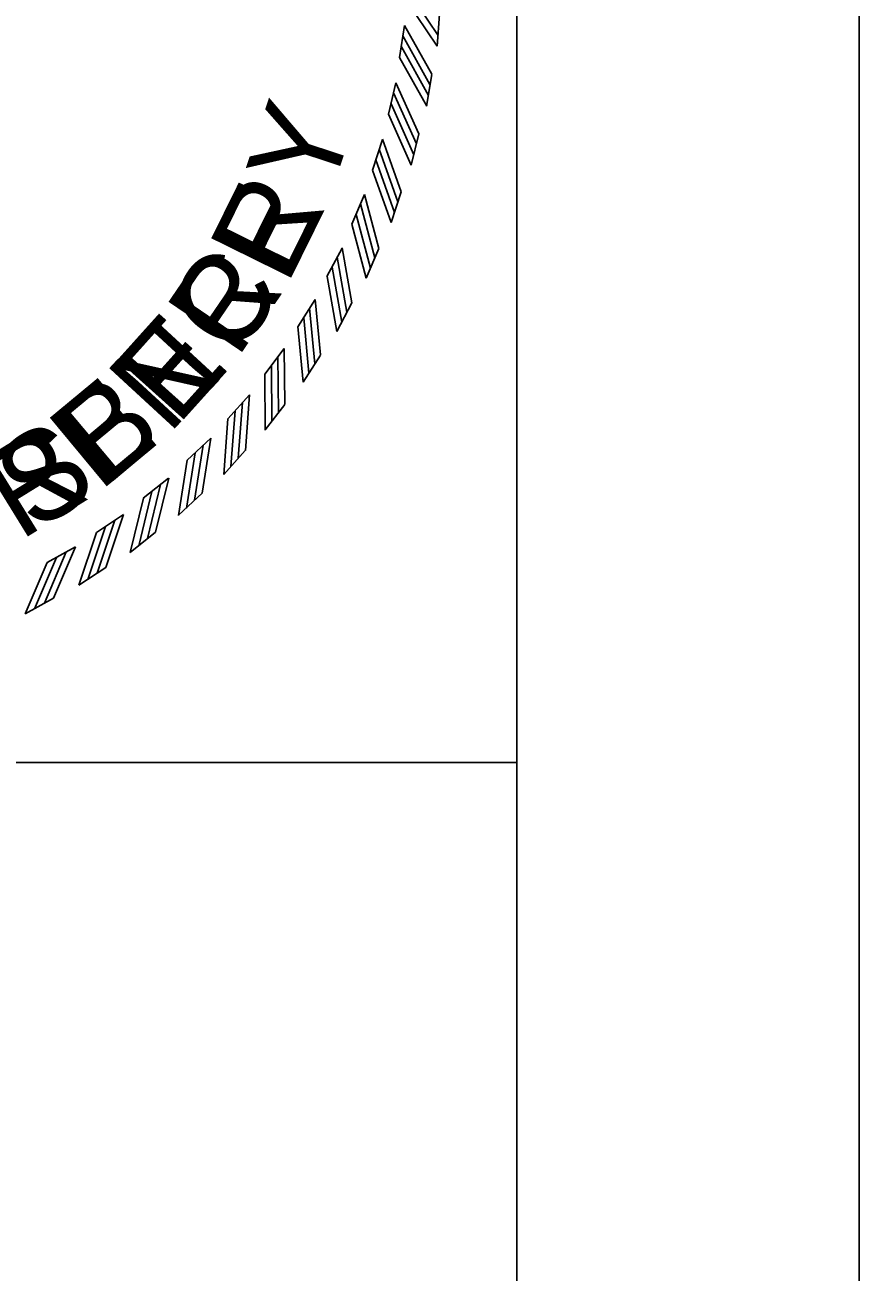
# Model space of a CAD drawing. Extents: x 0 to 1228740, y 0 to 152440.
# Drawn here: x 32.593 to 34, y 16.545 to 18.649 of the extents above; entities that cross this region are included whole.
import ezdxf

# ---------------------------------------------------------------- set-up
doc = ezdxf.new("R2010")
doc.units = 0
for name, color, linetype in [('R_Border', 7, 'Continuous'), ('R_No Plot', 7, 'Continuous'), ('STAMP_BOL', 7, 'Continuous'), ('STAMP_PP', 7, 'Continuous')]:
    doc.layers.add(name, color=color, linetype=linetype)

msp = doc.modelspace()

# ---------------------------------------------------------------- linework, layer by layer
at = {"layer": 'R_Border'}
msp.add_line((33.4231, 0.5768), (33.4231, 21.4232), dxfattribs=at)
msp.add_line((33.4231, 0.5768), (33.4231, 21.4232), dxfattribs=at)
for points in [[(33.9999, 22), (0, 22), (0, 0), (33.9999, 0)], [(1.516, 21.4232), (33.4231, 21.4232), (33.4231, 0.5768), (1.516, 0.5768)], [(1.516, 21.4232), (33.4231, 21.4232), (33.4231, 0.5768), (1.516, 0.5768)]]:
    msp.add_lwpolyline(points, close=True, dxfattribs=at)
at = {"layer": 'R_No Plot'}
for points in [[(33.4231, 17.4052), (33.4231, 10.8708), (1.516, 10.8708), (1.516, 21.4232), (25.1971, 21.4232), (25.1971, 20.4352), (28.7491, 20.4352), (28.7491, 20.0782), (29.1131, 20.0782), (29.1131, 20.1432), (30.6665, 20.1432)], [(30.6665, 20.1432), (30.6665, 17.4052), (33.4231, 17.4052)]]:
    msp.add_lwpolyline(points, dxfattribs=at)
at = {"layer": 'STAMP_BOL'}
for p, q in [((33.2925, 18.6677), (33.2885, 18.6135)), ((33.2337, 18.6484), (33.2252, 18.5945)), ((33.2793, 18.566), (33.2708, 18.5123)), ((33.2191, 18.5516), (33.2062, 18.4986)), ((33.1965, 18.4563), (33.1793, 18.4046)), ((33.2577, 18.4657), (33.2449, 18.4129)), ((33.1662, 18.3633), (33.1447, 18.3131)), ((33.228, 18.3676), (33.2108, 18.316)), ((33.1283, 18.273), (33.1027, 18.2248)), ((33.1902, 18.2722), (33.1688, 18.2222)), ((33.083, 18.1863), (33.0536, 18.1403)), ((33.1447, 18.1803), (33.1192, 18.1323)), ((33.0308, 18.1035), (32.9977, 18.0601)), ((33.0917, 18.0925), (33.0624, 18.0467)), ((32.9719, 18.0253), (32.9353, 17.9849)), ((33.0317, 18.0093), (32.9987, 17.9661)), ((32.9067, 17.9523), (32.8669, 17.915)), ((32.965, 17.9314), (32.9286, 17.8911)), ((32.8357, 17.8849), (32.793, 17.851)), ((32.8922, 17.8593), (32.8525, 17.8221)), ((32.7595, 17.8236), (32.7141, 17.7933)), ((32.8136, 17.7934), (32.7709, 17.7596)), ((32.6784, 17.7688), (32.6306, 17.7424)), ((32.7298, 17.7342), (32.6845, 17.704)), ((32.6414, 17.6822), (32.5938, 17.6558))]:
    msp.add_line(p, q, dxfattribs=at)
for points in [[(33.2378, 18.7098), (33.29, 18.6315)], [(33.2363, 18.6917), (33.2885, 18.6134)], [(33.2336, 18.6484), (33.2793, 18.5661)], [(33.2307, 18.6312), (33.2764, 18.5488)], [(33.2282, 18.6124), (33.2739, 18.5301)], [(33.2252, 18.5945), (33.2709, 18.5122)], [(33.219, 18.5517), (33.2577, 18.4658)], [(33.2107, 18.5162), (33.2493, 18.4304)], [(33.2147, 18.5347), (33.2534, 18.4489)], [(33.2062, 18.4986), (33.2449, 18.4128)], [(33.1965, 18.4564), (33.228, 18.3677)], [(33.1908, 18.4398), (33.2223, 18.3511)], [(33.1852, 18.4218), (33.2167, 18.3331)], [(33.1793, 18.4046), (33.2108, 18.3159)], [(33.1591, 18.3473), (33.1832, 18.2563)], [(33.1662, 18.3634), (33.1902, 18.2723)], [(33.1521, 18.3298), (33.1761, 18.2388)], [(33.1448, 18.3132), (33.1688, 18.2222)], [(33.1282, 18.2731), (33.1447, 18.1804)], [(33.1199, 18.2577), (33.1364, 18.165)], [(33.1028, 18.2249), (33.1193, 18.1322)], [(33.1114, 18.2408), (33.1279, 18.1481)], [(33.083, 18.1863), (33.0917, 18.0926)], [(33.0734, 18.1717), (33.0822, 18.0779)], [(33.0537, 18.1404), (33.0624, 18.0466)], [(33.0636, 18.1555), (33.0723, 18.0618)], [(33.0308, 18.1036), (33.0317, 18.0094)], [(33.0089, 18.0745), (33.0098, 17.9803)], [(33.02, 18.0898), (33.021, 17.9956)], [(32.9977, 18.0602), (32.9987, 17.966)], [(32.96, 18.0125), (32.9532, 17.9186)], [(32.9719, 18.0254), (32.9651, 17.9315)], [(32.9477, 17.9982), (32.9408, 17.9043)], [(32.9354, 17.9849), (32.9286, 17.891)], [(32.9067, 17.9524), (32.8922, 17.8594)], [(32.8803, 17.9273), (32.8658, 17.8343)], [(32.8938, 17.9405), (32.8793, 17.8475)], [(32.867, 17.915), (32.8525, 17.822)], [(32.8358, 17.885), (32.8136, 17.7935)], [(32.8219, 17.8742), (32.7998, 17.7827)], [(32.7931, 17.851), (32.7709, 17.7595)], [(32.8074, 17.8621), (32.7852, 17.7706)], [(32.7595, 17.8237), (32.7298, 17.7343)], [(32.7293, 17.8032), (32.6997, 17.7139)], [(32.7448, 17.8141), (32.7152, 17.7247)], [(32.7142, 17.7933), (32.6845, 17.704)], [(32.663, 17.7605), (32.6261, 17.6739)], [(32.6784, 17.7688), (32.6415, 17.6823)], [(32.6307, 17.7424), (32.5938, 17.6558)], [(32.6467, 17.751), (32.6097, 17.6644)]]:
    msp.add_lwpolyline(points, dxfattribs=at)
at = {"layer": 'STAMP_PP'}
for p, q in [((33.2925, 18.6677), (33.2885, 18.6135)), ((33.2337, 18.6484), (33.2252, 18.5945)), ((33.2793, 18.566), (33.2708, 18.5123)), ((33.2191, 18.5516), (33.2062, 18.4986)), ((33.1965, 18.4563), (33.1793, 18.4046)), ((33.2577, 18.4657), (33.2449, 18.4129)), ((33.1662, 18.3633), (33.1447, 18.3131)), ((33.228, 18.3676), (33.2108, 18.316)), ((33.1283, 18.273), (33.1027, 18.2248)), ((33.1902, 18.2722), (33.1688, 18.2222)), ((33.083, 18.1863), (33.0536, 18.1403)), ((33.1447, 18.1803), (33.1192, 18.1323)), ((33.0308, 18.1035), (32.9977, 18.0601)), ((33.0917, 18.0925), (33.0624, 18.0467)), ((32.9719, 18.0253), (32.9353, 17.9849)), ((33.0317, 18.0093), (32.9987, 17.9661)), ((32.9067, 17.9523), (32.8669, 17.915)), ((32.965, 17.9314), (32.9286, 17.8911)), ((32.8357, 17.8849), (32.793, 17.851)), ((32.8922, 17.8593), (32.8525, 17.8221)), ((32.7595, 17.8236), (32.7141, 17.7933)), ((32.8136, 17.7934), (32.7709, 17.7596)), ((32.6784, 17.7688), (32.6306, 17.7424)), ((32.7298, 17.7342), (32.6845, 17.704)), ((32.6414, 17.6822), (32.5938, 17.6558))]:
    msp.add_line(p, q, dxfattribs=at)
for points in [[(33.2378, 18.7098), (33.29, 18.6315)], [(33.2363, 18.6917), (33.2885, 18.6134)], [(33.2336, 18.6484), (33.2793, 18.5661)], [(33.2307, 18.6312), (33.2764, 18.5488)], [(33.2282, 18.6124), (33.2739, 18.5301)], [(33.2252, 18.5945), (33.2709, 18.5122)], [(33.219, 18.5517), (33.2577, 18.4658)], [(33.2107, 18.5162), (33.2493, 18.4304)], [(33.2147, 18.5347), (33.2534, 18.4489)], [(33.2062, 18.4986), (33.2449, 18.4128)], [(33.1965, 18.4564), (33.228, 18.3677)], [(33.1908, 18.4398), (33.2223, 18.3511)], [(33.1852, 18.4218), (33.2167, 18.3331)], [(33.1793, 18.4046), (33.2108, 18.3159)], [(33.1591, 18.3473), (33.1832, 18.2563)], [(33.1662, 18.3634), (33.1902, 18.2723)], [(33.1521, 18.3298), (33.1761, 18.2388)], [(33.1448, 18.3132), (33.1688, 18.2222)], [(33.1282, 18.2731), (33.1447, 18.1804)], [(33.1199, 18.2577), (33.1364, 18.165)], [(33.1028, 18.2249), (33.1193, 18.1322)], [(33.1114, 18.2408), (33.1279, 18.1481)], [(33.083, 18.1863), (33.0917, 18.0926)], [(33.0734, 18.1717), (33.0822, 18.0779)], [(33.0537, 18.1404), (33.0624, 18.0466)], [(33.0636, 18.1555), (33.0723, 18.0618)], [(33.0308, 18.1036), (33.0317, 18.0094)], [(33.0089, 18.0745), (33.0098, 17.9803)], [(33.02, 18.0898), (33.021, 17.9956)], [(32.9977, 18.0602), (32.9987, 17.966)], [(32.96, 18.0125), (32.9532, 17.9186)], [(32.9719, 18.0254), (32.9651, 17.9315)], [(32.9477, 17.9982), (32.9408, 17.9043)], [(32.9354, 17.9849), (32.9286, 17.891)], [(32.9067, 17.9524), (32.8922, 17.8594)], [(32.8803, 17.9273), (32.8658, 17.8343)], [(32.8938, 17.9405), (32.8793, 17.8475)], [(32.867, 17.915), (32.8525, 17.822)], [(32.8358, 17.885), (32.8136, 17.7935)], [(32.8219, 17.8742), (32.7998, 17.7827)], [(32.7931, 17.851), (32.7709, 17.7595)], [(32.8074, 17.8621), (32.7852, 17.7706)], [(32.7595, 17.8237), (32.7298, 17.7343)], [(32.7293, 17.8032), (32.6997, 17.7139)], [(32.7448, 17.8141), (32.7152, 17.7247)], [(32.7142, 17.7933), (32.6845, 17.704)], [(32.663, 17.7605), (32.6261, 17.6739)], [(32.6784, 17.7688), (32.6415, 17.6823)], [(32.6307, 17.7424), (32.5938, 17.6558)], [(32.6467, 17.751), (32.6097, 17.6644)]]:
    msp.add_lwpolyline(points, dxfattribs=at)

# ---------------------------------------------------------------- texts
at = {"layer": 'STAMP_BOL'}
for s, rotation, p in [('E', 63.7362, (33.0351, 18.2082)), ('C', 56.0754, (32.9507, 18.0835)), ('N', 47.3202, (32.8349, 17.9563)), ('E', 39.6594, (32.7186, 17.8605)), ('R', 31.6338, (32.5843, 17.7778))]:
    msp.add_text(s, height=0.1503, rotation=rotation, dxfattribs=at).set_placement(p)
at = {"layer": 'STAMP_PP'}
for s, rotation, p in [('Y', 71.7733, (33.1072, 18.3567)), ('R', 63.7477, (33.0384, 18.2148)), ('R', 55.7221, (32.9504, 18.084)), ('E', 48.0613, (32.8502, 17.9717)), ('B', 40.0357, (32.7301, 17.8695)), ('S', 32.7397, (32.6095, 17.7919))]:
    msp.add_text(s, height=0.1503, rotation=rotation, dxfattribs=at).set_placement(p)

doc.saveas('drawing.dxf')
